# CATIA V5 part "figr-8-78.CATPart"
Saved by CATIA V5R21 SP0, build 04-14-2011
Part number: Part1
Bounding box of the stored display mesh (mm): x -35 to 35, y -116.369 to 116.369, z 0 to 117.647
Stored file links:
  D:\CATIA V5R21 E-RESOURCES\CATIA-V5R21\catia-v5r21-prt\c08-catia-v5r20-prt\c08-catia-v5r21-figr-8-78.CATPart
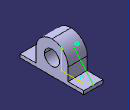
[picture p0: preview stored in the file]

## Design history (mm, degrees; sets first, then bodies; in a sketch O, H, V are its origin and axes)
Body1 (main body)
  Sketch1 on yz-plane, origin (0, 0, 0), H (0, 1, 0), V (0, 0, 1)
    line L1 (0, 0) -> (116.3687, 0)
    point P1 (116.3687, 0)
    line L2 (116.3687, 0) -> (116.3687, 12.5279)
    point P2 (116.3687, 12.5279)
    line L3 (116.3687, 12.5279) -> (58.943, 12.5279)
    point P3 (58.943, 12.5279)
    line L4 (58.943, 12.5279) -> (58.943, 58.7038)
    point P4 (58.943, 58.7038)
    arc A1 centre (0, 58.7038) radius 58.943 from (58.943, 58.7038) to (0, 117.6467) ccw
    point P5 (0, 58.7038)
    point P6 (-58.943, 58.7038)
    line L5 (-58.943, 58.7038) -> (-58.943, 12.5279)
    point P7 (-58.943, 12.5279)
    axis line L6 (0, 0) -> (0, 108.1111)
    point P9 (0, 117.6467)
    point P10 (0, 117.6467)
    point P11 (-58.943, 58.7038)
    arc A2 centre (0, 58.7038) radius 58.943 from (-58.943, 58.7038) to (0, 117.6467) cw
    point P13 (-58.943, 12.5279)
    point P14 (-116.3687, 12.5279)
    line L7 (-116.3687, 12.5279) -> (-58.943, 12.5279)
    point P15 (-116.3687, 0)
    line L8 (-116.3687, 0) -> (-116.3687, 12.5279)
    point P16 (0, 0)
    line L9 (0, 0) -> (-116.3687, 0)
    circle A3 centre (0, 58.7038) radius 27.1825
    horizontal: L1 H, L3 H
    vertical: L2 V, L4 V, L6 V
    tangency: A1 L4, L5 A1
    coincidence: P7 L3, P5 V, L6 P9, P6 P11, O P16, P9 P10, P7 P13
    symmetry: P9 P10 L6, P4 P11 L6, A1 A2 L6, P3 P13 L6, P2 P14 L6, L3 L7 L6, P1 P15 L6, L2 L8 L6, O P16 L6, L1 L9 L6
  Pad1: profile Sketch1, direction (1, 0, 0), length 35, mirrored extent
  Sketch2 on yz-plane, origin (0, 0, 0), H (0, 1, 0), V (0, 0, 1)
    line L1 (116.3687, 12.5279) -> (44.9741, 96.8037)
    point P1 (116.3687, 12.5279)
    point P2 (44.9741, 96.8037)
    reference projected arc E1 centre (0, 58.7038) radius 58.943 from (58.943, 58.7038) to (0, 117.6467) ccw from edge [face of Pad1 | face of Pad1]
    reference projected arc E2 centre (0, 58.7038) radius 58.943 from (58.943, 58.7038) to (0, 117.6467) ccw from edge [face of Pad1 | face of Pad1]
    reference projected point E3 (116.3687, 12.5279) from vertex [face of Pad1 | face of Pad1 | face of Pad1]
    tangency: L1 E1
    coincidence: P2 E2, P1 E3
  Stiffener1: ExtendedProfile Sketch2, ThicknessTop 0, ThicknessValue 15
